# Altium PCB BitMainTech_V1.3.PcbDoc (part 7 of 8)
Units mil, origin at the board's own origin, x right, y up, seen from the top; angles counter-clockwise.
Board outline 9842.52 x 6082.68 mil, 4 copper layers (Top Layer, Mid-Layer 1, Mid-Layer 2, Bottom Layer); 987 components, 282 nets, 3694 pads, 3174 vias.
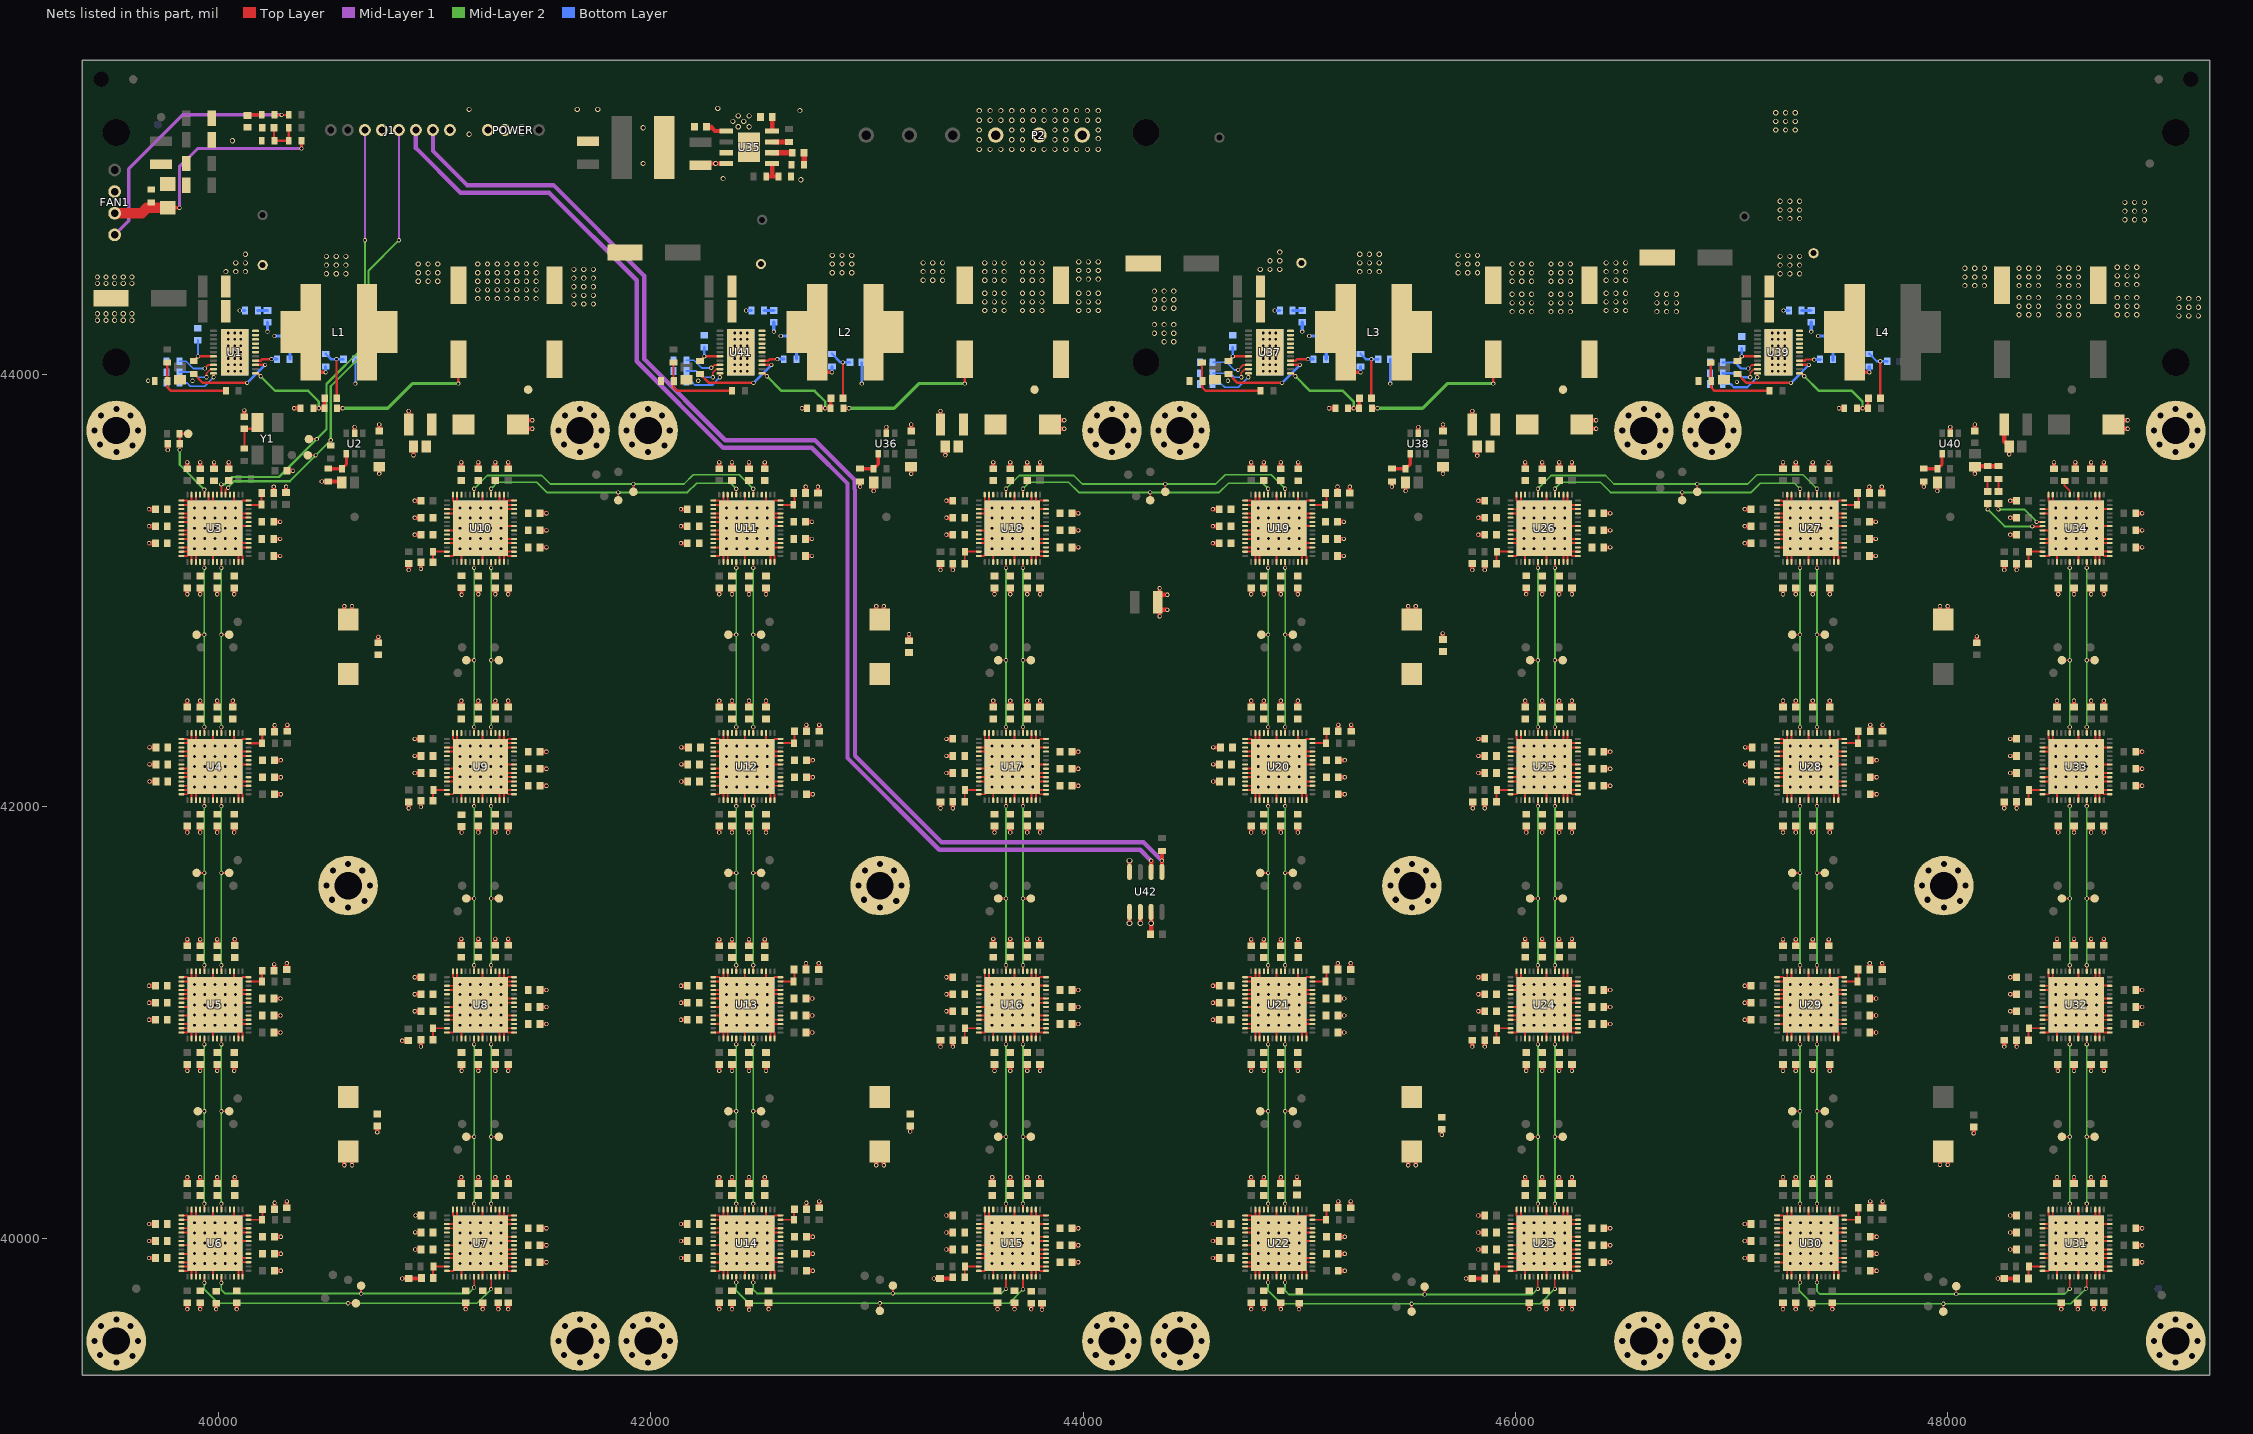
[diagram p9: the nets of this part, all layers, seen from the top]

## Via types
v1: diameter 19, hole 12, Top Layer to Bottom Layer, 1347 vias
v2: diameter 25.98, hole 12.99, Top Layer to Bottom Layer, 800 vias
v3: diameter 24, hole 16, Top Layer to Bottom Layer, 778 vias
v4: diameter 50, hole 28, Top Layer to Bottom Layer, 160 vias
v5: diameter 19.68, hole 11.81, Top Layer to Bottom Layer, 84 vias
v6: diameter 26, hole 18, Top Layer to Bottom Layer, 5 vias

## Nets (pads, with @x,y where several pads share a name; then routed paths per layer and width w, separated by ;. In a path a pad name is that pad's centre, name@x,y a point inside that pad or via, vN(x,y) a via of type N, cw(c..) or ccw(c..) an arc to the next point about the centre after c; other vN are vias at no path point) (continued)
GND: (continued)
  other v4: 39527.56,39427.56 41673.23,39427.56 41988.19,39427.56 44133.86,39427.56 44448.82,39427.56 46594.49,39427.56 46909.45,39427.56 49055.12,39427.56 39602.56,39457.56 41748.23,39457.56 42063.19,39457.56 44208.86,39457.56 44523.82,39457.56 46669.49,39457.56 46984.45,39457.56 49130.12,39457.56 39452.56,39462.56 41598.23,39462.56 41913.19,39462.56 44058.86,39462.56 44373.82,39462.56 46519.49,39462.56 46834.45,39462.56 48980.12,39462.56 39427.56,39527.56 39627.56,39527.56 41573.23,39527.56 41773.23,39527.56 41888.19,39527.56 42088.19,39527.56 44033.86,39527.56 44233.86,39527.56 44348.82,39527.56 44548.82,39527.56 46494.49,39527.56 46694.49,39527.56 46809.45,39527.56 47009.45,39527.56 48955.12,39527.56 49155.12,39527.56 39457.56,39597.56 39592.56,39597.56 41603.23,39597.56 41738.23,39597.56 41918.19,39597.56 42053.19,39597.56 44063.86,39597.56 44198.86,39597.56 44378.82,39597.56 44513.82,39597.56 46524.49,39597.56 46659.49,39597.56 46839.45,39597.56 46974.45,39597.56 48985.12,39597.56 49120.12,39597.56 39527.56,39627.56 41673.23,39627.56 41988.19,39627.56 44133.86,39627.56 44448.82,39627.56 46594.49,39627.56 46909.45,39627.56 49055.12,39627.56 40600.39,41533.86 43061.02,41533.86 45521.67,41533.86 47982.28,41533.86 40675.39,41563.86 43136.02,41563.86 45596.67,41563.86 48057.28,41563.86 40525.39,41568.86 42986.02,41568.86 45446.67,41568.86 47907.28,41568.86 40500.39,41633.86 40700.39,41633.86 42961.02,41633.86 43161.02,41633.86 45421.67,41633.86 45621.67,41633.86 47882.28,41633.86 48082.28,41633.86 40530.39,41703.86 40665.39,41703.86 42991.02,41703.86 43126.02,41703.86 45451.67,41703.86 45586.67,41703.86 47912.28,41703.86 48047.28,41703.86 40600.39,41733.86 43061.02,41733.86 45521.67,41733.86 47982.28,41733.86 39527.56,43640.16 41673.23,43640.16 41988.19,43640.16 44133.86,43640.16 44448.82,43640.16 46594.49,43640.16 46909.45,43640.16 49055.12,43640.16 39602.56,43670.16 41748.23,43670.16 42063.19,43670.16 44208.86,43670.16 44523.82,43670.16 46669.49,43670.16 46984.45,43670.16 49130.12,43670.16 39452.56,43675.16 41598.23,43675.16 41913.19,43675.16 44058.86,43675.16 44373.82,43675.16 46519.49,43675.16 46834.45,43675.16 48980.12,43675.16 39427.56,43740.16 39627.56,43740.16 41573.23,43740.16 41773.23,43740.16 41888.19,43740.16 42088.19,43740.16 44033.86,43740.16 44233.86,43740.16 44348.82,43740.16 44548.82,43740.16 46494.49,43740.16 46694.49,43740.16 46809.45,43740.16 47009.45,43740.16 48955.12,43740.16 49155.12,43740.16 39457.56,43810.16 39592.56,43810.16 41603.23,43810.16 41738.23,43810.16 41918.19,43810.16 42053.19,43810.16 44063.86,43810.16 44198.86,43810.16 44378.82,43810.16 44513.82,43810.16 46524.49,43810.16 46659.49,43810.16 46839.45,43810.16 46974.45,43810.16 48985.12,43810.16 49120.12,43810.16 39527.56,43840.16 41673.23,43840.16 41988.19,43840.16 44133.86,43840.16 44448.82,43840.16 46594.49,43840.16 46909.45,43840.16 49055.12,43840.16
  other v5: 40045.28,44013.78 40074.8,44013.78 40104.33,44013.78 42387.8,44013.78 42417.32,44013.78 42446.85,44013.78 44833.46,44013.78 44862.99,44013.78 44892.52,44013.78 47187.8,44013.78 47217.32,44013.78 47246.85,44013.78 40045.28,44043.31 40074.8,44043.31 40104.33,44043.31 42387.8,44043.31 42417.32,44043.31 42446.85,44043.31 44833.46,44043.31 44862.99,44043.31 44892.52,44043.31 47187.8,44043.31 47217.32,44043.31 47246.85,44043.31 40045.28,44072.83 40074.8,44072.83 40104.33,44072.83 42387.8,44072.83 42417.32,44072.83 42446.85,44072.83 44833.46,44072.83 44862.99,44072.83 44892.52,44072.83 47187.8,44072.83 47217.32,44072.83 47246.85,44072.83 40045.28,44102.36 40074.8,44102.36 40104.33,44102.36 42387.8,44102.36 42417.32,44102.36 42446.85,44102.36 44833.46,44102.36 44862.99,44102.36 44892.52,44102.36 47187.8,44102.36 47217.32,44102.36 47246.85,44102.36 40045.28,44131.89 40074.8,44131.89 40104.33,44131.89 42387.8,44131.89 42417.32,44131.89 42446.85,44131.89 44833.46,44131.89 44862.99,44131.89 44892.52,44131.89 47187.8,44131.89 47217.32,44131.89 47246.85,44131.89 40045.28,44161.42 40074.8,44161.42 40104.33,44161.42 42387.8,44161.42 42417.32,44161.42 42446.85,44161.42 44833.46,44161.42 44862.99,44161.42 44892.52,44161.42 47187.8,44161.42 47217.32,44161.42 47246.85,44161.42 40045.28,44190.94 40074.8,44190.94 40104.33,44190.94 42387.8,44190.94 42417.32,44190.94 42446.85,44190.94 44833.46,44190.94 44862.99,44190.94 44892.52,44190.94 47187.8,44190.94 47217.32,44190.94 47246.85,44190.94
  other v6: 44315,41460
LL1: C11.2 C12.1 L1.1 R1.1 U1.6 U1.7 U1.8 U1.9 U1.10 U1.11 | length 183
  Top Layer w15: L1.1@40454,44009 v1(40496.06,44009)
  Bottom Layer w15: v1(40227,44197) C12.1@40227,44240.44 ; v1@40259,44177.17 C11.2@40330,44177.17 ; v1(40496.06,44009) R1.1@40496.06,44035.47
  other v1: 40259,44177
LL2: C558.2 C559.1 L2.1 R64.1 U41.6 U41.7 U41.8 U41.9 U41.10 U41.11 | length 185.5
  Top Layer w15: L2.1@42796.52,44009 v1(42838.58,44009)
  Bottom Layer w15: v1(42569.52,44197) C559.1@42569.52,44240.44 ; v1@42601.52,44177.17 C558.2@42675,44177.17 ; v1(42838.58,44009) R64.1@42838.58,44035.47
  other v1: 42601.52,44177
LL3: C574.2 C575.1 L3.1 R36.1 U37.6 U37.7 U37.8 U37.9 U37.10 U37.11 | length 190.6
  Top Layer w15: L3.1@45241.4,44009 v1(45283.46,44009)
  Bottom Layer w15: v1(45014.4,44197) C575.1@45014.4,44240.44 ; v1@45046.4,44177.17 C574.2@45125,44177.17 ; v1(45283.46,44009) R36.1@45283.46,44035.47
  other v1: 45046.4,44177
LL4: C590.2 C591.1 L4.1 R50.1 U39.6 U39.7 U39.8 U39.9 U39.10 U39.11 | length 181.2
  Top Layer w15: L4.1@47595.73,44009 v1(47637.8,44009)
  Bottom Layer w15: v1(47368.73,44197) C591.1@47368.73,44240.44 ; v1@47400.73,44177.17 C590.2@47470,44177.17 ; v1(47637.8,44009) R50.1@47637.8,44035.47
  other v1: 47400.73,44177
NetC1_2: C1.2 C10.1 R1.2 | length 273.1
  Top Layer w11: v1(40546.54,44070) C10.1@40547.24,43889.76
  Bottom Layer w11: R1.2@40496.06,44094.53 40520.59,44070 v1(40546.54,44070) C1.2@40578.74,44070
NetC10_2: C10.2 R3.2 R12.1 U1.1 | length 474.3
  Top Layer w11: U1.1@40172.05,44003.94 40182.06,44003.94 v1(40195,43991)
  Top Layer w15: R12.1@40438.98,43842.52 R3.2@40490.16,43842.52 C10.2@40490.16,43887.8
  Mid-Layer 2 w11: v1(40195,43991) 40263,43923 40415.58,43923 40464.57,43874.02 v1(40464.57,43842.52)
NetC11_1: C11.1 R4.2 | length 52.4
  Bottom Layer w15: R4.2@40330.71,44070 C11.1@40330.71,44122.44
NetC12_2: C12.2 R11.1 | length 43.9
  Bottom Layer w15: R11.1@40182.53,44295 C12.2@40226.44,44295
NetC13_1: C13.1 R6.1 U1.18 | length 174.7
  Top Layer w11: R6.1@39885.83,44062.99 v1(39905.51,44082.68) U1.18@39977.56,44082.68
  Bottom Layer w11: v1(39905.51,44082.68) C13.1@39905.51,44157.44
NetC22_2: C22.2 FB1.1 U3.55 | length 108.3
  Top Layer w10: U3.55@40139.76,43395.67 FB1.1@40196.85,43395.67 ; FB1.1@40198.82,43397.64 C22.2@40198.82,43448.82
NetC24_2: C24.2 FB2.1 U4.55 | length 114.2
  Top Layer w10: U4.55@40139.76,42293.31 FB2.1@40202.76,42293.31 C24.2@40202.76,42344.49
NetC26_2: C26.2 FB3.1 U5.55 | length 108.3
  Top Layer w10: U5.55@40139.76,41190.94 FB3.1@40200.79,41190.94 C26.2@40200.79,41238.19
NetC28_2: C28.2 FB4.1 U6.55 | length 114.2
  Top Layer w9: U6.55@40139.76,40088.58 40204.72,40088.58 C28.2@40204.72,40137.8
NetC30_1: C30.1 R17.2 Y1.3 | length 131.9
  Top Layer w10: R17.2@40120.08,43657.48 C30.1@40120.08,43748.03 Y1.3@40161.42,43748.03
NetC89_2: C89.2 FB5.1 U7.55 | length 114.2
  Top Layer w9: C89.2@40992.13,39822.83 40992.13,39872.05 U7.55@41057.09,39872.05
NetC91_2: C91.2 FB6.1 U8.55 | length 114.2
  Top Layer w9: C91.2@40992.13,40925.2 FB6.1@40992.13,40974.41 U8.55@41057.09,40974.41
NetC93_2: C93.2 FB7.1 U9.55 | length 114.2
  Top Layer w9: C93.2@40992.13,42027.56 40992.13,42076.77 U9.55@41057.09,42076.77
NetC95_2: C95.2 FB8.1 U10.55 | length 114.2
  Top Layer w9: C95.2@40992.13,43129.92 FB8.1@40992.13,43179.13 U10.55@41057.09,43179.13
NetC157_2: C157.2 FB9.1 U11.55 | length 114.2
  Top Layer w9: U11.55@42600.39,43395.67 42665.35,43395.67 C157.2@42665.35,43444.88
NetC159_2: C159.2 FB10.1 U12.55 | length 114.2
  Top Layer w9: U12.55@42600.39,42293.31 42665.35,42293.31 C159.2@42665.35,42342.52
NetC161_2: C161.2 FB11.1 U13.55 | length 114.2
  Top Layer w9: U13.55@42600.39,41190.94 42665.35,41190.94 C161.2@42665.35,41240.16
NetC163_2: C163.2 FB12.1 U14.55 | length 110.2
  Top Layer w9: U14.55@42600.39,40088.58 FB12.1@42663.39,40088.58 C163.2@42663.39,40135.83
NetC221_2: C221.2 FB13.1 U15.55 | length 114.2
  Top Layer w9: C221.2@43452.76,39822.83 43452.76,39872.05 U15.55@43517.72,39872.05
NetC223_2: C223.2 FB14.1 U16.55 | length 114.2
  Top Layer w9: C223.2@43452.76,40925.2 43452.76,40974.41 U16.55@43517.72,40974.41
NetC225_2: C225.2 FB15.1 U17.55 | length 114.2
  Top Layer w9: C225.2@43452.76,42027.56 43452.76,42076.77 U17.55@43517.72,42076.77
NetC227_2: C227.2 FB16.1 U18.55 | length 114.2
  Top Layer w9: C227.2@43452.76,43129.92 43452.76,43179.13 U18.55@43517.72,43179.13
NetC289_2: C289.2 FB17.1 U19.55 | length 114.2
  Top Layer w9: U19.55@45061.02,43395.67 45125.98,43395.67 C289.2@45125.98,43444.88
NetC291_2: C291.2 FB18.1 U20.55 | length 114.2
  Top Layer w9: U20.55@45061.02,42293.31 45125.98,42293.31 C291.2@45125.98,42342.52
NetC293_2: C293.2 FB19.1 U21.55 | length 114.2
  Top Layer w9: U21.55@45061.02,41190.94 45125.98,41190.94 C293.2@45125.98,41240.16
NetC295_2: C295.2 FB20.1 U22.55 | length 114.2
  Top Layer w9: U22.55@45061.02,40088.58 45125.98,40088.58 C295.2@45125.98,40137.8
NetC353_2: C353.2 FB21.1 U23.55 | length 114.2
  Top Layer w9: C353.2@45913.39,39822.83 45913.39,39872.05 U23.55@45978.35,39872.05
NetC355_2: C355.2 FB22.1 U24.55 | length 114.2
  Top Layer w9: C355.2@45913.39,40925.2 45913.39,40974.41 U24.55@45978.35,40974.41
NetC357_2: C357.2 FB23.1 U25.55 | length 114.2
  Top Layer w9: C357.2@45913.39,42027.56 45913.39,42076.77 U25.55@45978.35,42076.77
NetC359_2: C359.2 FB24.1 U26.55 | length 114.2
  Top Layer w9: C359.2@45913.39,43129.92 45913.39,43179.13 U26.55@45978.35,43179.13
NetC421_2: C421.2 FB25.1 U27.55 | length 114.2
  Top Layer w9: U27.55@47521.65,43395.67 47586.61,43395.67 C421.2@47586.61,43444.88
NetC423_2: C423.2 FB26.1 U28.55 | length 114.2
  Top Layer w9: U28.55@47521.65,42293.31 47586.61,42293.31 C423.2@47586.61,42342.52
NetC425_2: C425.2 FB27.1 U29.55 | length 114.2
  Top Layer w9: U29.55@47521.65,41190.94 47586.61,41190.94 C425.2@47586.61,41240.16
NetC427_2: C427.2 FB28.1 U30.55 | length 114.2
  Top Layer w9: U30.55@47521.65,40088.58 47586.61,40088.58 C427.2@47586.61,40137.8
NetC485_2: C485.2 FB29.1 U31.55 | length 114.2
  Top Layer w9: C485.2@48374.02,39822.83 48374.02,39872.05 U31.55@48438.98,39872.05
NetC487_2: C487.2 FB30.1 U32.55 | length 114.2
  Top Layer w9: C487.2@48374.02,40925.2 48374.02,40974.41 U32.55@48438.98,40974.41
NetC489_2: C489.2 FB31.1 U33.55 | length 114.2
  Top Layer w9: C489.2@48374.02,42027.56 48374.02,42076.77 U33.55@48438.98,42076.77
NetC491_2: C491.2 FB32.1 U34.55 | length 114.2
  Top Layer w9: C491.2@48374.02,43129.92 48374.02,43179.13 U34.55@48438.98,43179.13
NetC549_2: C549.2 D1.2 FAN1.2 FB33.1 FB34.1 R70.2
NetC551_1: C551.1 U35.1 | length 99.4
  Top Layer w20: C551.1@42257.56,45145 42277.56,45145 42297.56,45125 U35.1@42348.7,45125
NetC551_2: C551.2 L5.1 U35.3
NetC552_1: C552.1 U35.8 | length 63.7
  Top Layer w20: U35.8@42562.56,45126.26 C552.1@42562.56,45190
NetC557_1: C557.1 C598.2 R64.2 | length 264.3
  Top Layer w11: C557.1@42889.76,43889.76 v1@42889.76,44055
  Bottom Layer w11: R64.2@42838.58,44094.53 42878.11,44055 v1(42889.06,44055) C598.2@42921.26,44055
NetC557_2: C557.2 R33.1 R66.2 U41.1 | length 474.3
  Top Layer w11: U41.1@42514.57,44003.94 42524.58,44003.94 v1(42537.52,43991)
  Top Layer w15: R33.1@42781.5,43842.52 R66.2@42832.68,43842.52 C557.2@42832.68,43887.8
  Mid-Layer 2 w11: v1(42537.52,43991) 42605.52,43923 42758.1,43923 42807.09,43874.02 v1(42807.09,43842.52)
NetC558_1: C558.1 R67.2 | length 59.1
  Bottom Layer w15: R67.2@42674.53,44070 C558.1@42674.53,44129.06
NetC559_2: C559.2 R32.1 | length 43.9
  Bottom Layer w15: R32.1@42525.05,44295 C559.2@42568.96,44295
NetC560_1: C560.1 R69.1 U41.18 | length 142.2
  Top Layer w11: R69.1@42228.35,44062.99 v1(42248.03,44082.68) U41.18@42320.08,44082.68
  Bottom Layer w11: v1(42248.03,44082.68) C560.1@42248.03,44125
NetC564_2: C564.2 C573.1 R36.2 | length 272.8
  Top Layer w11: C573.1@45333.94,43890 v1(45333.94,44070)
  Bottom Layer w11: R36.2@45283.46,44094.53 45307.99,44070 v1(45333.94,44070) C564.2@45366.14,44070
NetC573_2: C573.2 R38.2 R47.1 U37.1 | length 474.3
  Top Layer w11: U37.1@44959.45,44003.94 44969.46,44003.94 v1(44982.4,43991)
  Top Layer w15: R47.1@45226.38,43842.52 R38.2@45277.56,43842.52 C573.2@45277.56,43887.8
  Mid-Layer 2 w11: v1(44982.4,43991) 45050.4,43923 45202.98,43923 45251.97,43874.02 v1(45251.97,43842.52)
NetC574_1: C574.1 R39.2 | length 52.4
  Bottom Layer w15: R39.2@45125,44070 C574.1@45125,44122.44
NetC575_2: C575.2 R46.1 | length 43.9
  Bottom Layer w15: R46.1@44969.93,44295 C575.2@45013.84,44295
NetC576_1: C576.1 R41.1 U37.18 | length 142.2
  Top Layer w11: R41.1@44673.23,44062.99 v1(44692.91,44082.68) U37.18@44764.96,44082.68
  Bottom Layer w11: v1(44692.91,44082.68) C576.1@44692.91,44125
NetC580_2: C580.2 C589.1 R50.2 | length 267
  Top Layer w11: C589.1@47688.28,43890 v1(47688.28,44060)
  Bottom Layer w11: R50.2@47637.8,44094.53 47672.32,44060 v1(47688.28,44060) C580.2@47720.47,44060
NetC589_2: C589.2 R52.2 R61.1 U39.1 | length 474.3
  Top Layer w11: U39.1@47313.78,44003.94 47323.8,44003.94 v1(47336.73,43991)
  Top Layer w15: R61.1@47580.71,43842.52 R52.2@47631.89,43842.52 C589.2@47631.89,43887.8
  Mid-Layer 2 w11: v1(47336.73,43991) 47404.73,43923 47557.31,43923 47606.3,43874.02 v1(47606.3,43842.52)
NetC590_1: C590.1 R53.2 | length 57.4
  Bottom Layer w15: R53.2@47470,44065 C590.1@47470,44122.44
NetC591_2: C591.2 R60.1 | length 43.9
  Bottom Layer w15: R60.1@47324.26,44295 C591.2@47368.17,44295
NetC592_1: C592.1 R55.1 U39.18 | length 137.2
  Top Layer w11: R55.1@47027.56,44062.99 v1(47047.24,44082.68) U39.18@47119.29,44082.68
  Bottom Layer w11: v1(47047.24,44082.68) C592.1@47047.24,44120
NetC603_1: C603.1 U35.6 | length 91.9
  Top Layer w24: U35.6@42562.52,45025 C603.1@42654.41,45025
NetC603_2: C603.2 R73.2 | length 55
  Top Layer w25: R73.2@42709.53,44970 C603.2@42709.53,45025
NetC604_1: C604.1 R23.2 R24.1 R25.2 | length 184
  Top Layer w10: R25.2@40257.56,45081.97 C604.1@40257.56,45140 ; R25.2@40259.53,45080 R23.2@40325.47,45080 R24.1@40325.47,45140
NetC605_1: C605.1 R26.1 | length 63
  Top Layer w15: C605.1@40137.44,45200 R26.1@40200.47,45200
NetD1_1: D1.1 FAN1.3 R23.1 R70.1 | length 1135.4
  Top Layer w15: D1.1@39765,44769.88 v1(39819.88,44769.88) ; v1(40384.53,45044.53) R23.1@40384.53,45080
  Top Layer w50: FAN1.3@39520,44745 39645,44745 39669.88,44769.88 D1.1@39765,44769.88
  Mid-Layer 1 w15: v1(39819.88,44769.88) 39819.88,44959.88 39904.53,45044.53 v1(40384.53,45044.53)
NetFAN1_4: FAN1.4 R26.2 R27.1 | length 1208.9
  Top Layer w10: R26.2@40259.53,45200 R27.1@40325.47,45200
  Mid-Layer 1 w15: FAN1.4@39520,44645 39585,44710 39585,44950 39835,45200 v1(40292.5,45200)
NetR2_2: R2.2 R5.1 R7.1 | length 390.8
  Top Layer w11: R7.1@39763,43970.53 R2.2@39763,44054.47 ; R7.1@39764.53,43969 39764.53,43938.47 39780,43923 R5.1@40034.47,43923
NetR4_1: R4.1 U1.4 | length 101.3
  Top Layer w11: U1.4@40172.05,44062.99 40196.99,44062.99 40204,44070 v1(40245.5,44070)
  Bottom Layer w15: v1(40245.5,44070) R4.1@40270.47,44070
NetR6_2: R6.2 U1.3 | length 426.1
  Top Layer w11: R6.2@39885.83,44001.97 39927.8,43960 v1(40133,43960) ; U1.3@40172.05,44043.31 v1(40216,44043.31)
  Bottom Layer w11: v1@40132.85,43960.15 v1(40216,44043.31)
NetR8_1: R8.1 U1.20 | length 178.7
  Top Layer w8: v1(39936.65,44026.65) 39953.31,44043.31 U1.20@39977.56,44043.31
  Bottom Layer w8: R8.1@39819.53,44060 39850,44060 39883.35,44026.65 v1(39936.65,44026.65)
NetR9_1: R9.1 U1.22 | length 199.2
  Top Layer w8: v1(39977.56,43986) U1.22@39977.56,44003.94
  Bottom Layer w8: R9.1@39819.53,43960 39855,43960 39870,43945 39936.56,43945 v1(39977.56,43986)
NetR10_1: R10.1 U1.21 | length 194.7
  Top Layer w8: v1@39944.88,43986 39944.88,44004.88 39963.62,44023.62 U1.21@39977.56,44023.62
  Bottom Layer w8: R10.1@39819.53,44010 39880,44010 39904,43986 v1(39945,43986)
NetR13_1: R13.1 R14.2 U2.4 | length 140.9
  Top Layer w15: R14.2@40507.87,43562.99 R13.1@40570.87,43562.99 40592.52,43584.65 U2.4@40592.52,43631.89
NetR19_2: R19.2 TF.2 | length 57.9
  Top Layer w10: TF.2@48235,43457.56 R19.2@48235,43515.47
NetR20_2: R20.2 RF.2 | length 57.9
  Top Layer w10: RF.2@48185,43457.56 R20.2@48185,43515.47
NetR22_1: R22.1 U35.7 | length 77.5
  Top Layer w23: U35.7@42562.52,45075 R22.1@42640,45075
NetR28_1: R28.1 R65.2 R68.1 | length 390.8
  Top Layer w11: R28.1@42105.52,43970.53 R65.2@42105.52,44054.47 ; R28.1@42107.05,43969 42107.05,43938.47 42122.52,43923 R68.1@42376.99,43923
NetR29_1: R29.1 U41.20 | length 179.8
  Top Layer w8: v1(42279.98,44030) 42279.98,44027.47 42295.83,44043.31 U41.20@42320.08,44043.31
  Bottom Layer w8: R29.1@42164.53,44065 42200,44065 42235.81,44029.19 42279.17,44029.19 v1(42279.98,44030)
NetR30_1: R30.1 U41.22 | length 194.6
  Top Layer w8: v1(42320.08,43986) U41.22@42320.08,44003.94
  Bottom Layer w8: R30.1@42164.53,43965 42190,43965 42205,43950 42284.08,43950 v1(42320.08,43986)
NetR31_1: R31.1 U41.21 | length 195.8
  Top Layer w8: v1@42287.4,43986 42287.4,44007.4 42303.62,44023.62 U41.21@42320.08,44023.62
  Bottom Layer w8: R31.1@42164.53,44015 42210,44015 42239,43986 v1(42287.52,43986)
NetR34_1: R34.1 R35.2 U36.4 | length 140.9
  Top Layer w15: R35.2@42968.5,43562.99 R34.1@43031.5,43562.99 43053.15,43584.65 U36.4@43053.15,43631.89
NetR37_2: R37.2 R40.1 R42.1 | length 390.8
  Top Layer w11: R42.1@44550.4,43970.53 R37.2@44550.4,44054.47 ; R42.1@44551.93,43969 44551.93,43938.47 44567.4,43923 R40.1@44821.87,43923
NetR39_1: R39.1 U37.4 | length 108.9
  Top Layer w11: U37.4@44959.45,44062.99 44984.39,44062.99 44991.4,44070 v1(45041,44070)
  Bottom Layer w15: v1(45041,44070) R39.1@45065.47,44070
NetR41_2: R41.2 U37.3 | length 426.1
  Top Layer w11: R41.2@44673.23,44001.97 44715.2,43960 v1(44920.4,43960) ; U37.3@44959.45,44043.31 v1(45003.4,44043.31)
  Bottom Layer w11: v1@44920.25,43960.15 v1(45003.4,44043.31)
NetR43_1: R43.1 U37.20 | length 189.6
  Top Layer w8: v1(44717.4,44020) 44740.71,44043.31 U37.20@44764.96,44043.31
  Bottom Layer w8: R43.1@44599.53,44055 44665,44055 44700,44020 v1(44717.4,44020)
NetR44_1: R44.1 U37.22 | length 208.6
  Top Layer w8: v1(44764.96,43986) U37.22@44764.96,44003.94
  Bottom Layer w8: R44.1@44599.53,43955 44640,43955 44655,43940 44718.96,43940 v1(44764.96,43986)
NetR45_1: R45.1 U37.21 | length 201.5
  Top Layer w8: v1@44732.28,43986 44732.28,44007.28 44748.62,44023.62 U37.21@44764.96,44023.62
  Bottom Layer w8: R45.1@44599.53,44005 44680,44005 44699,43986 v1(44732.4,43986)
NetR48_1: R48.1 R49.2 U38.4 | length 140.9
  Top Layer w15: R49.2@45429.13,43562.99 R48.1@45492.13,43562.99 45513.78,43584.65 U38.4@45513.78,43631.89
NetR51_2: R51.2 R54.1 R56.1 | length 390.8
  Top Layer w11: R56.1@46904.73,43970.53 R51.2@46904.73,44054.47 ; R56.1@46906.26,43969 46906.26,43938.47 46921.73,43923 R54.1@47176.2,43923
NetR53_1: R53.1 U39.4 | length 103
  Top Layer w11: U39.4@47313.78,44062.99 47338.72,44062.99 47343.73,44068 v1(47382,44068) v1@47385,44065
  Bottom Layer w15: v1(47382,44068) R53.1@47410.47,44068
NetR55_2: R55.2 U39.3 | length 426.1
  Top Layer w11: R55.2@47027.56,44001.97 47069.53,43960 v1(47274.73,43960) ; U39.3@47313.78,44043.31 v1(47357.73,44043.31)
  Bottom Layer w11: v1@47274.58,43960.15 v1(47357.73,44043.31)
NetR57_1: R57.1 U39.20 | length 178.4
  Top Layer w8: v1(47078.39,44026.65) 47095.04,44043.31 U39.20@47119.29,44043.31
  Bottom Layer w10: R57.1@46959.53,44055 47015.86,44055 47044.21,44026.65 v1(47078.39,44026.65)
NetR58_1: R58.1 U39.22 | length 203
  Top Layer w8: v1(47119.29,43986) U39.22@47119.29,44003.94
  Bottom Layer w10: R58.1@46959.53,43955 46995,43955 47010,43940 47073.29,43940 v1(47119.29,43986)
NetR59_1: R59.1 U39.21 | length 195.4
  Top Layer w8: v1@47086.61,43986 47086.61,44006.61 47103.62,44023.62 U39.21@47119.29,44023.62
  Bottom Layer w10: R59.1@46959.53,44005 47030,44005 47049,43986 v1(47086.73,43986)
NetR62_1: R62.1 R63.2 U40.4 | length 140.9
  Top Layer w15: R63.2@47889.76,43562.99 R62.1@47952.76,43562.99 47974.41,43584.65 U40.4@47974.41,43631.89
NetR67_1: R67.1 U41.4 | length 103.8
  Top Layer w11: U41.4@42514.57,44062.99 42545,44062.99 42552.01,44070 v1(42585.99,44070)
  Bottom Layer w15: v1(42585.99,44070) R67.1@42615.47,44070
NetR69_2: R69.2 U41.3 | length 426.1
  Top Layer w11: R69.2@42228.35,44001.97 42270.32,43960 v1(42475.52,43960) ; U41.3@42514.57,44043.31 v1(42558.52,44043.31)
  Bottom Layer w11: v1@42475.37,43960.15 v1(42558.52,44043.31)
NetR71_2: R71.2 R72.2 U35.5 | length 110
  Top Layer w20: R71.2@42535,44914.53 R72.2@42590,44914.53 ; 42562.52,44920 U35.5@42562.52,44975
NetRF_1: RF.1 U34.49 | length 314.3
  Top Layer w10: v1(48185,43375) RF.1@48185,43402.44 ; v1(48391.43,43296.43) 48438.16,43296.43 U34.49@48438.98,43297.24
  Mid-Layer 2 w10: v1(48185,43375) 48263.57,43296.43 v1(48391.43,43296.43)
NetTF_1: TF.1 U34.48 | length 255.5
  Top Layer w10: v1(48235,43375) TF.1@48235,43402.44 ; v1(48411.93,43316.93) U34.48@48438.98,43316.93
  Mid-Layer 2 w10: v1(48235,43375) 48353.86,43375 v1(48411.93,43316.93)
RI1: TP10.1 U3.37 U4.6 | length 827.5
  Top Layer w8: U4.6@40013.78,42340.55 v1(40013.78,42368.11) ; v1(40013.78,42795.28) TP10.1@40049.96,42795.28 ; v1(40013.78,43104.33) U3.37@40013.78,43131.89
  Mid-Layer 2 w8: v1(40013.78,42368.11) v1(40013.78,43104.33)
RI2: TP12.1 U4.37 U5.6 | length 827.5
  Top Layer w8: U5.6@40013.78,41238.19 v1(40013.78,41265.75) ; v1(40013.78,41692.91) TP12.1@40049.96,41692.91 ; v1(40013.78,42001.97) U4.37@40013.78,42029.53
  Mid-Layer 2 w8: v1(40013.78,41265.75) v1(40013.78,42001.97)
RI3: TP14.1 U5.37 U6.6 | length 827.5
  Top Layer w8: U6.6@40013.78,40135.83 v1(40013.78,40163.39) ; v1(40013.78,40590.55) TP14.1@40049.96,40590.55 ; v1(40013.78,40899.61) U5.37@40013.78,40927.17
  Mid-Layer 2 w8: v1(40013.78,40163.39) v1(40013.78,40899.61)
RI4: TP16.1 U6.37 U7.6 | length 1334.6
  Top Layer w8: v1(40013.78,39797.24) U6.37@40013.78,39824.8 ; v1(40660,39747) TP16.1@40660,39783.18 ; v1(41183.07,39775) U7.6@41183.07,39824.8
  Mid-Layer 2 w8: v1(40013.78,39797.24) 40013.78,39764.22 40031,39747 41155.07,39747 v1(41183.07,39775)
RI5: TP34.1 U7.37 U8.6 | length 882.6
  Top Layer w8: TP34.1@41146.89,40472.44 v1(41183.07,40472.44) ; U7.37@41183.07,40135.83 v1(41183.07,40163.39) U7.37@41183.07,40135.83 ; v1(41183.07,40899.61) U8.6@41183.07,40927.17 v1(41183.07,40899.61)
  Mid-Layer 2 w8: v1(41183.07,40163.39) v1(41183.07,40899.61)
RI6: TP36.1 U8.37 U9.6 | length 882.6
  Top Layer w8: TP36.1@41146.89,41574.8 v1(41183.07,41574.8) ; U8.37@41183.07,41238.19 v1(41183.07,41265.75) U8.37@41183.07,41238.19 ; v1(41183.07,42001.97) U9.6@41183.07,42029.53 v1(41183.07,42001.97)
  Mid-Layer 2 w8: v1(41183.07,41265.75) v1(41183.07,42001.97)
RI7: TP38.1 U9.37 U10.6 | length 827.5
  Top Layer w8: TP38.1@41146.89,42677.17 v1(41183.07,42677.17) ; U9.37@41183.07,42340.55 v1(41183.07,42368.11) ; v1(41183.07,43104.33) U10.6@41183.07,43131.89
  Mid-Layer 2 w8: v1(41183.07,42368.11) v1(41183.07,43104.33)
RI8: TP40.1 U10.37 U11.6 | length 1468.9
  Top Layer w8: U10.37@41183.07,43442.91 v1(41183.07,43470.47) ; TP40.1@41920,43456.13 v1(41920,43492.31) ; U11.6@42474.41,43442.91 v1(42474.41,43470.47)
  Mid-Layer 2 w8: v1(41183.07,43470.47) 41244.09,43531.5 41496.06,43531.5 41535.25,43492.31 42153.73,43492.31 42196.85,43535.43 42409.45,43535.43 v1(42474.41,43470.47)
RI9: TP54.1 U11.37 U12.6 | length 882.6
  Top Layer w8: v1(42474.41,42795.28) TP54.1@42510.59,42795.28 ; U12.6@42474.41,42340.55 v1(42474.41,42368.11) U12.6@42474.41,42340.55 ; v1(42474.41,43104.33) U11.37@42474.41,43131.89 v1(42474.41,43104.33)
  Mid-Layer 2 w8: v1(42474.41,42368.11) v1(42474.41,43104.33)
RI10: TP56.1 U12.37 U13.6 | length 882.6
  Top Layer w8: v1(42474.41,41692.91) TP56.1@42510.59,41692.91 ; U13.6@42474.41,41238.19 v1(42474.41,41265.75) U13.6@42474.41,41238.19 ; v1(42474.41,42001.97) U12.37@42474.41,42029.53 v1(42474.41,42001.97)
  Mid-Layer 2 w8: v1(42474.41,41265.75) v1(42474.41,42001.97)
RI11: TP58.1 U13.37 U14.6 | length 882.6
  Top Layer w8: v1(42474.41,40590.55) TP58.1@42510.59,40590.55 ; U14.6@42474.41,40135.83 v1(42474.41,40163.39) U14.6@42474.41,40135.83 ; v1(42474.41,40899.61) U13.37@42474.41,40927.17 v1(42474.41,40899.61)
  Mid-Layer 2 w8: v1(42474.41,40163.39) v1(42474.41,40899.61)
RI12: TP60.1 U14.37 U15.6 | length 1338.9
  Top Layer w8: v1(42474.22,39798.05) U14.37@42474.22,39825.61 ; v1(43120.44,39747.8) TP60.1@43120.44,39783.98 ; v1(43643.51,39768.46) U15.6@43643.51,39825.61
  Mid-Layer 2 w8: v1(42474.22,39798.05) 42474.22,39765.02 42491.44,39747.8 43622.85,39747.8 v1(43643.51,39768.46)
RI13: TP76.1 U15.37 U16.6 | length 855.1
  Top Layer w8: TP76.1@43607.52,40472.44 v1(43643.7,40472.44) ; U15.37@43643.7,40135.83 v1(43643.7,40163.39) ; v1(43643.7,40899.61) U16.6@43643.7,40927.17 v1(43643.7,40899.61)
  Mid-Layer 2 w8: v1(43643.7,40163.39) v1(43643.7,40899.61)
RI14: TP78.1 U16.37 U17.6 | length 882.6
  Top Layer w8: TP78.1@43607.52,41574.8 v1(43643.7,41574.8) ; U16.37@43643.7,41238.19 v1(43643.7,41265.75) U16.37@43643.7,41238.19 ; v1(43643.7,42001.97) U17.6@43643.7,42029.53 v1(43643.7,42001.97)
  Mid-Layer 2 w8: v1(43643.7,41265.75) v1(43643.7,42001.97)
RI15: TP80.1 U17.37 U18.6 | length 882.6
  Top Layer w8: TP80.1@43607.52,42677.17 v1(43643.7,42677.17) ; U17.37@43643.7,42340.55 v1(43643.7,42368.11) U17.37@43643.7,42340.55 ; v1(43643.7,43104.33) U18.6@43643.7,43131.89 v1(43643.7,43104.33)
  Mid-Layer 2 w8: v1(43643.7,42368.11) v1(43643.7,43104.33)
RI16: TP74.1 U18.37 U19.6 | length 1468.9
  Top Layer w8: U18.37@43643.7,43442.91 v1(43643.7,43470.47) ; TP74.1@44380.63,43456.13 v1(44380.63,43492.31) ; U19.6@44935.31,43443.66 v1@44935.31,43471.22
  Mid-Layer 2 w8: v1(43643.7,43470.47) 43704.72,43531.5 43956.69,43531.5 43995.88,43492.31 44614.36,43492.31 44657.48,43535.43 44870.08,43535.43 v1(44935.04,43470.47)
RI17: TP94.1 U19.37 U20.6 | length 882.6
  Top Layer w8: v1(44935.04,42795.28) TP94.1@44971.22,42795.28 ; U20.6@44935.04,42340.55 v1(44935.04,42368.11) U20.6@44935.04,42340.55 ; v1(44935.04,43104.33) U19.37@44935.04,43131.89 v1(44935.04,43104.33)
  Mid-Layer 2 w8: v1(44935.04,42368.11) v1(44935.04,43104.33)
RI18: TP96.1 U20.37 U21.6 | length 882.6
  Top Layer w8: v1(44935.04,41692.91) TP96.1@44971.22,41692.91 ; U21.6@44935.04,41238.19 v1(44935.04,41265.75) U21.6@44935.04,41238.19 ; v1(44935.04,42001.97) U20.37@44935.04,42029.53 v1(44935.04,42001.97)
  Mid-Layer 2 w8: v1(44935.04,41265.75) v1(44935.04,42001.97)
RI19: TP98.1 U21.37 U22.6 | length 882.6
  Top Layer w8: v1(44935.04,40590.55) TP98.1@44971.22,40590.55 ; U22.6@44935.04,40135.83 v1(44935.04,40163.39) U22.6@44935.04,40135.83 ; v1(44935.04,40899.61) U21.37@44935.04,40927.17 v1(44935.04,40899.61)
  Mid-Layer 2 w8: v1(44935.04,40163.39) v1(44935.04,40899.61)
RI20: TP100.1 U22.37 U23.6 | length 1345.9
  Top Layer w8: v1(44934.85,39798.05) U22.37@44934.85,39825.61 ; v1(45580,39742.8) TP100.1@45580,39778.98 ; v1(46104.14,39768.46) U23.6@46104.14,39825.61
  Mid-Layer 2 w8: v1(44934.85,39798.05) 44934.85,39760.15 44952.2,39742.8 46078.48,39742.8 v1(46104.14,39768.46)
RI21: TP114.1 U23.37 U24.6 | length 882.6
  Top Layer w8: TP114.1@46068.15,40472.44 v1(46104.33,40472.44) ; U23.37@46104.33,40135.83 v1(46104.33,40163.39) U23.37@46104.33,40135.83 ; v1(46104.33,40899.61) U24.6@46104.33,40927.17 v1(46104.33,40899.61)
  Mid-Layer 2 w8: v1(46104.33,40163.39) v1(46104.33,40899.61)
RI22: TP116.1 U24.37 U25.6 | length 882.6
  Top Layer w8: TP116.1@46068.15,41574.8 v1(46104.33,41574.8) ; U24.37@46104.33,41238.19 v1(46104.33,41265.75) U24.37@46104.33,41238.19 ; v1(46104.33,42001.97) U25.6@46104.33,42029.53 v1(46104.33,42001.97)
  Mid-Layer 2 w8: v1(46104.33,41265.75) v1(46104.33,42001.97)
RI23: TP118.1 U25.37 U26.6 | length 883.9
  Top Layer w8: TP118.1@46068.15,42677.17 v1(46104.33,42677.17) ; U25.37@46104.33,42340.55 v1(46104.33,42368.11) U25.37@46104.33,42340.55 ; v1(46104.33,43104.33) U26.6@46104.33,43131.89 v1(46104.33,43104.33)
  Mid-Layer 2 w8: v1(46104.33,42368.11) 46104.33,43077.36 46105.85,43078.88 46105.85,43102.81 v1(46104.33,43104.33)
RI24: TP120.1 U26.37 U27.6 | length 1468.9
  Top Layer w8: U26.37@46104.33,43442.91 v1(46104.33,43470.47) ; TP120.1@46841.26,43456.13 v1(46841.26,43492.31) ; U27.6@47395.67,43442.91 v1(47395.67,43470.47)
  Mid-Layer 2 w8: v1(46104.33,43470.47) 46165.35,43531.5 46417.32,43531.5 46456.51,43492.31 47074.99,43492.31 47118.11,43535.43 47330.71,43535.43 v1(47395.67,43470.47)
RI25: TP134.1 U27.37 U28.6 | length 882.6
  Top Layer w8: v1(47395.67,42795.28) TP134.1@47431.85,42795.28 ; U28.6@47395.67,42340.55 v1(47395.67,42368.11) U28.6@47395.67,42340.55 ; v1(47395.67,43104.33) U27.37@47395.67,43131.89 v1(47395.67,43104.33)
  Mid-Layer 2 w8: v1(47395.67,42368.11) v1(47395.67,43104.33)
RI26: TP136.1 U28.37 U29.6 | length 855.1
  Top Layer w8: U29.6@47395.67,41238.19 v1(47395.67,41265.75) ; v1(47395.67,41692.91) TP136.1@47431.85,41692.91 ; v1(47395.67,42001.97) U28.37@47395.67,42029.53 v1(47395.67,42001.97)
  Mid-Layer 2 w8: v1(47395.67,41265.75) v1(47395.67,42001.97)
RI27: TP138.1 U29.37 U30.6 | length 882.6
  Top Layer w8: v1(47395.67,40590.55) TP138.1@47431.85,40590.55 ; U30.6@47395.67,40135.83 v1(47395.67,40163.39) U30.6@47395.67,40135.83 ; v1(47395.67,40899.61) U29.37@47395.67,40927.17 v1(47395.67,40899.61)
  Mid-Layer 2 w8: v1(47395.67,40163.39) v1(47395.67,40899.61)
RI28: TP140.1 U30.37 U31.6 | length 1345
  Top Layer w8: v1(47395.48,39798.05) U30.37@47395.48,39825.61 ; v1(48040,39745) TP140.1@48040,39781.18 ; v1(48564.77,39768.46) U31.6@48564.77,39825.61
  Mid-Layer 2 w8: v1(47395.48,39798.05) 47395.48,39758.56 47409.04,39745 47921.08,39745 48541.31,39745 v1(48564.77,39768.46)
RI29: TP153.1 U31.37 U32.6 | length 827.5
  Top Layer w8: TP153.1@48528.78,40472.44 v1(48564.96,40472.44) ; U31.37@48564.96,40135.83 v1(48564.96,40163.39) ; v1(48564.96,40899.61) U32.6@48564.96,40927.17
  Mid-Layer 2 w8: v1(48564.96,40163.39) v1(48564.96,40899.61)
RI30: TP155.1 U32.37 U33.6 | length 882.6
  Top Layer w8: TP155.1@48528.78,41574.8 v1(48564.96,41574.8) ; U32.37@48564.96,41238.19 v1(48564.96,41265.75) U32.37@48564.96,41238.19 ; v1(48564.96,42001.97) U33.6@48564.96,42029.53 v1(48564.96,42001.97)
  Mid-Layer 2 w8: v1(48564.96,41265.75) v1(48564.96,42001.97)
RI31: TP157.1 U33.37 U34.6 | length 882.6
  Top Layer w8: TP157.1@48528.78,42677.17 v1(48564.96,42677.17) ; U33.37@48564.96,42340.55 v1(48564.96,42368.11) U33.37@48564.96,42340.55 ; v1(48564.96,43104.33) U34.6@48564.96,43131.89 v1(48564.96,43104.33)
  Mid-Layer 2 w8: v1(48564.96,42368.11) v1(48564.96,43104.33)
RI32: R21.1 U34.37 | length 72.8
  Top Layer w9: R21.1@48541.34,43505.91 48541.34,43483.66 48564.96,43460.04 U34.37@48564.96,43442.91
RST: C31.1 R18.1 TP28.1 U3.10 | length 356.1
  Top Layer w10: v1(39820.87,43649.61) R18.1@39820.87,43712.6 ; R18.1@39820.87,43724.41 TP28.1@39860,43724.41 ; U3.10@39935.04,43442.91 v1(39935.04,43466.54)
  Mid-Layer 2 w10: v1(39820.87,43649.61) 39820.87,43580.71 v1(39935.04,43466.54)
RST1: TP17.1 U3.33 U4.10 | length 827.5
  Top Layer w8: TP17.1@39898.86,42795.28 v1(39935.04,42795.28) ; U4.10@39935.04,42340.55 v1(39935.04,42368.11) ; v1(39935.04,43104.33) U3.33@39935.04,43131.89
  Mid-Layer 2 w8: v1(39935.04,42368.11) v1(39935.04,43104.33)
RST2: TP19.1 U4.33 U5.10 | length 882.6
  Top Layer w8: TP19.1@39898.86,41692.91 v1(39935.04,41692.91) ; U5.10@39935.04,41238.19 v1(39935.04,41265.75) U5.10@39935.04,41238.19 ; v1(39935.04,42001.97) U4.33@39935.04,42029.53 v1(39935.04,42001.97)
  Mid-Layer 2 w8: v1(39935.04,41265.75) v1(39935.04,42001.97)
RST3: TP21.1 U5.33 U6.10 | length 882.6
  Top Layer w8: TP21.1@39898.86,40590.55 v1(39935.04,40590.55) ; U6.10@39935.04,40135.83 v1(39935.04,40163.39) U6.10@39935.04,40135.83 ; v1(39935.04,40899.61) U5.33@39935.04,40927.17 v1(39935.04,40899.61)
  Mid-Layer 2 w8: v1(39935.04,40163.39) v1(39935.04,40899.61)
RST4: TP23.1 U6.33 U7.10 | length 1532
  Top Layer w8: v1(39935.04,39797.24) U6.33@39935.04,39824.8 ; v1(40600,39702) TP23.1@40636.18,39702 ; v1(41261.81,39767.66) U7.10@41261.81,39824.8
  Mid-Layer 2 w8: v1(39935.04,39797.24) 39935.04,39767.11 40000.15,39702 41196.15,39702 v1(41261.81,39767.66)
RST5: TP41.1 U7.33 U8.10 | length 882.6
  Top Layer w8: v1(41261.81,40472.44) TP41.1@41297.99,40472.44 ; U7.33@41261.81,40135.83 v1(41261.81,40163.39) U7.33@41261.81,40135.83 ; v1(41261.81,40899.61) U8.10@41261.81,40927.17 v1(41261.81,40899.61)
  Mid-Layer 2 w8: v1(41261.81,40163.39) v1(41261.81,40899.61)
RST6: TP43.1 U8.33 U9.10 | length 882.6
  Top Layer w8: v1(41261.81,41574.8) TP43.1@41297.99,41574.8 ; U8.33@41261.81,41238.19 v1(41261.81,41265.75) U8.33@41261.81,41238.19 ; v1(41261.81,42001.97) U9.10@41261.81,42029.53 v1(41261.81,42001.97)
  Mid-Layer 2 w8: v1(41261.81,41265.75) v1(41261.81,42001.97)
RST7: TP45.1 U9.33 U10.10 | length 882.6
  Top Layer w8: v1(41261.81,42677.17) TP45.1@41297.99,42677.17 ; U9.33@41261.81,42340.55 v1(41261.81,42368.11) U9.33@41261.81,42340.55 ; v1(41261.81,43104.33) U10.10@41261.81,43131.89 v1(41261.81,43104.33)
  Mid-Layer 2 w8: v1(41261.81,42368.11) v1(41261.81,43104.33)
RST8: TP47.1 U10.33 U11.10 | length 1285
  Top Layer w8: U10.33@41261.81,43442.91 v1(41261.81,43470.47) ; TP47.1@41850,43417.13 v1(41850,43453.31) ; U11.10@42395.67,43442.91 v1(42395.67,43470.47)
  Mid-Layer 2 w8: v1(41261.81,43470.47) 41291.34,43500 41472.44,43500 41519.13,43453.31 42169.85,43453.31 42212.6,43496.06 42370.08,43496.06 v1(42395.67,43470.47)
RST9: TP61.1 U11.33 U12.10 | length 882.6
  Top Layer w8: TP61.1@42359.49,42795.28 v1(42395.67,42795.28) ; U12.10@42395.67,42340.55 v1(42395.67,42368.11) U12.10@42395.67,42340.55 ; v1(42395.67,43104.33) U11.33@42395.67,43131.89 v1(42395.67,43104.33)
  Mid-Layer 2 w8: v1(42395.67,42368.11) v1(42395.67,43104.33)
RST10: TP63.1 U12.33 U13.10 | length 882.6
  Top Layer w8: TP63.1@42359.49,41692.91 v1(42395.67,41692.91) ; U13.10@42395.67,41238.19 v1(42395.67,41265.75) U13.10@42395.67,41238.19 ; v1(42395.67,42001.97) U12.33@42395.67,42029.53 v1(42395.67,42001.97)
  Mid-Layer 2 w8: v1(42395.67,41265.75) v1(42395.67,42001.97)
RST11: TP65.1 U13.33 U14.10 | length 882.6
  Top Layer w8: TP65.1@42359.49,40590.55 v1(42395.67,40590.55) ; U14.10@42395.67,40135.83 v1(42395.67,40163.39) U14.10@42395.67,40135.83 ; v1(42395.67,40899.61) U13.33@42395.67,40927.17 v1(42395.67,40899.61)
  Mid-Layer 2 w8: v1(42395.67,40163.39) v1(42395.67,40899.61)
RST12: TP67.1 U14.33 U15.10 | length 1533.4
  Top Layer w8: v1(42395.48,39798.05) U14.33@42395.48,39825.61 ; TP67.1@43060.44,39666.62 v1(43060.44,39702.8) ; v1(43722.44,39766.36) U15.10@43722.44,39824.8
  Mid-Layer 2 w8: v1(42395.48,39798.05) 42395.48,39760.57 42453.25,39702.8 43658.89,39702.8 v1@43720,39763.92
RST13: TP83.1 U15.33 U16.10 | length 855.1
  Top Layer w8: U15.33@43722.44,40135.83 v1(43722.44,40163.39) ; v1(43722.44,40472.44) TP83.1@43758.62,40472.44 ; v1(43722.44,40899.61) U16.10@43722.44,40927.17 v1(43722.44,40899.61)
  Mid-Layer 2 w8: v1(43722.44,40163.39) v1(43722.44,40899.61)
RST14: TP85.1 U16.33 U17.10 | length 882.6
  Top Layer w8: v1(43722.44,41574.8) TP85.1@43758.62,41574.8 ; U16.33@43722.44,41238.19 v1(43722.44,41265.75) U16.33@43722.44,41238.19 ; v1(43722.44,42001.97) U17.10@43722.44,42029.53 v1(43722.44,42001.97)
  Mid-Layer 2 w8: v1(43722.44,41265.75) v1(43722.44,42001.97)
RST15: TP87.1 U17.33 U18.10 | length 882.6
  Top Layer w8: v1(43722.44,42677.17) TP87.1@43758.62,42677.17 ; U17.33@43722.44,42340.55 v1(43722.44,42368.11) U17.33@43722.44,42340.55 ; v1(43722.44,43104.33) U18.10@43722.44,43131.89 v1(43722.44,43104.33)
  Mid-Layer 2 w8: v1(43722.44,42368.11) v1(43722.44,43104.33)
RST16: TP81.1 U18.33 U19.10 | length 1285
  Top Layer w8: U18.33@43722.44,43442.91 v1(43722.44,43470.47) ; TP81.1@44310.63,43417.13 v1(44310.63,43453.31) ; U19.10@44856.57,43443.66 v1@44856.57,43471.22
  Mid-Layer 2 w8: v1(43722.44,43470.47) 43751.97,43500 43933.07,43500 43979.76,43453.31 44630.48,43453.31 44673.23,43496.06 44830.71,43496.06 v1(44856.3,43470.47)
RST17: TP101.1 U19.33 U20.10 | length 882.6
  Top Layer w8: TP101.1@44820.12,42795.28 v1(44856.3,42795.28) ; U20.10@44856.3,42340.55 v1(44856.3,42368.11) U20.10@44856.3,42340.55 ; v1(44856.3,43104.33) U19.33@44856.3,43131.89 v1(44856.3,43104.33)
  Mid-Layer 2 w8: v1(44856.3,42368.11) v1(44856.3,43104.33)
RST18: TP103.1 U20.33 U21.10 | length 855.1
  Top Layer w8: TP103.1@44820.12,41692.91 v1(44856.3,41692.91) ; U21.10@44856.3,41238.19 v1(44856.3,41265.75) ; v1(44856.3,42001.97) U20.33@44856.3,42029.53 v1(44856.3,42001.97)
  Mid-Layer 2 w8: v1(44856.3,41265.75) v1(44856.3,42001.97)
RST19: TP105.1 U21.33 U22.10 | length 882.6
  Top Layer w8: TP105.1@44820.12,40590.55 v1(44856.3,40590.55) ; U22.10@44856.3,40135.83 v1(44856.3,40163.39) U22.10@44856.3,40135.83 ; v1(44856.3,40899.61) U21.33@44856.3,40927.17 v1(44856.3,40899.61)
  Mid-Layer 2 w8: v1(44856.3,40163.39) v1(44856.3,40899.61)
RST20: TP107.1 U22.33 U23.10 | length 1538.6
  Top Layer w8: v1(44856.11,39798.05) U22.33@44856.11,39825.61 ; TP107.1@45520,39663.82 v1(45520,39700) ; v1(46182.88,39768.46) U23.10@46182.88,39825.61
  Mid-Layer 2 w8: v1(44856.11,39798.05) 44856.11,39760.57 44916.68,39700 46114.42,39700 v1(46182.88,39768.46)
RST21: TP121.1 U23.33 U24.10 | length 882.6
  Top Layer w8: v1(46183.07,40472.44) TP121.1@46219.25,40472.44 ; U23.33@46183.07,40135.83 v1(46183.07,40163.39) U23.33@46183.07,40135.83 ; v1(46183.07,40899.61) U24.10@46183.07,40927.17 v1(46183.07,40899.61)
  Mid-Layer 2 w8: v1(46183.07,40163.39) v1(46183.07,40899.61)
RST22: TP123.1 U24.33 U25.10 | length 882.6
  Top Layer w8: v1(46183.07,41574.8) TP123.1@46219.25,41574.8 ; U24.33@46183.07,41238.19 v1(46183.07,41265.75) U24.33@46183.07,41238.19 ; v1(46183.07,42001.97) U25.10@46183.07,42029.53 v1(46183.07,42001.97)
  Mid-Layer 2 w8: v1(46183.07,41265.75) v1(46183.07,42001.97)
RST23: TP125.1 U25.33 U26.10 | length 882.6
  Top Layer w8: v1(46183.07,42677.17) TP125.1@46219.25,42677.17 ; U25.33@46183.07,42340.55 v1(46183.07,42368.11) U25.33@46183.07,42340.55 ; v1(46183.07,43104.33) U26.10@46183.07,43131.89 v1(46183.07,43104.33)
  Mid-Layer 2 w8: v1(46183.07,42368.11) v1(46183.07,43104.33)
RST24: TP127.1 U26.33 U27.10 | length 1285
  Top Layer w8: U26.33@46183.07,43442.91 v1(46183.07,43470.47) ; TP127.1@46771.26,43417.13 v1(46771.26,43453.31) ; U27.10@47316.93,43442.91 v1(47316.93,43470.47)
  Mid-Layer 2 w8: v1(46183.07,43470.47) 46212.6,43500 46393.7,43500 46440.39,43453.31 47091.11,43453.31 47133.86,43496.06 47291.34,43496.06 v1(47316.93,43470.47)
RST25: TP141.1 U27.33 U28.10 | length 882.6
  Top Layer w8: TP141.1@47280.75,42795.28 v1(47316.93,42795.28) ; U28.10@47316.93,42340.55 v1(47316.93,42368.11) U28.10@47316.93,42340.55 ; v1(47316.93,43104.33) U27.33@47316.93,43131.89 v1(47316.93,43104.33)
  Mid-Layer 2 w8: v1(47316.93,42368.11) v1(47316.93,43104.33)
RST26: TP143.1 U28.33 U29.10 | length 882.6
  Top Layer w8: TP143.1@47280.75,41692.91 v1(47316.93,41692.91) ; U29.10@47316.93,41238.19 v1(47316.93,41265.75) U29.10@47316.93,41238.19 ; v1(47316.93,42001.97) U28.33@47316.93,42029.53 v1(47316.93,42001.97)
  Mid-Layer 2 w8: v1(47316.93,41265.75) v1(47316.93,42001.97)
RST27: TP145.1 U29.33 U30.10 | length 882.6
  Top Layer w8: TP145.1@47280.75,40590.55 v1(47316.93,40590.55) ; U30.10@47316.93,40135.83 v1(47316.93,40163.39) U30.10@47316.93,40135.83 ; v1(47316.93,40899.61) U29.33@47316.93,40927.17 v1(47316.93,40899.61)
  Mid-Layer 2 w8: v1(47316.93,40163.39) v1(47316.93,40899.61)
RST28: TP147.1 U30.33 U31.10 | length 1545.4
  Top Layer w8: v1(47316.74,39798.05) U30.33@47316.74,39825.61 ; TP147.1@47980,39663.82 v1(47980,39700) ; v1(48640,39770) 48643.51,39773.51 U31.10@48643.51,39825.61
  Mid-Layer 2 w8: v1(47316.74,39798.05) 47313.43,39794.73 47313.43,39760.39 47373.81,39700 48570,39700 v1(48640,39770) v1@48643.51,39773.51
RST29: TP158.1 U31.33 U32.10 | length 882.6
  Top Layer w8: v1(48643.7,40472.44) TP158.1@48679.88,40472.44 ; U31.33@48643.7,40135.83 v1(48643.7,40163.39) U31.33@48643.7,40135.83 ; v1(48643.7,40899.61) U32.10@48643.7,40927.17 v1(48643.7,40899.61)
  Mid-Layer 2 w8: v1(48643.7,40163.39) v1(48643.7,40899.61)
RST30: TP160.1 U32.33 U33.10 | length 882.6
  Top Layer w8: v1(48643.7,41574.8) TP160.1@48679.88,41574.8 ; U32.33@48643.7,41238.19 v1(48643.7,41265.75) U32.33@48643.7,41238.19 ; v1(48643.7,42001.97) U33.10@48643.7,42029.53 v1(48643.7,42001.97)
  Mid-Layer 2 w8: v1(48643.7,41265.75) v1(48643.7,42001.97)
RST31: TP162.1 U33.33 U34.10 | length 882.6
  Top Layer w8: v1(48643.7,42677.17) TP162.1@48679.88,42677.17 ; U33.33@48643.7,42340.55 v1(48643.7,42368.11) U33.33@48643.7,42340.55 ; v1(48643.7,43104.33) U34.10@48643.7,43131.89 v1(48643.7,43104.33)
  Mid-Layer 2 w8: v1(48643.7,42368.11) v1(48643.7,43104.33)
RXD: J1.3 TP27.1 U3.6 | length 2134.6
  Top Layer w8: TP27.1@40418.82,43700 v1(40455,43700)
  Top Layer w9: v1(40013.22,43490.34) 40013.46,43490.09 40013.46,43443.23 U3.6@40013.78,43442.91
  Mid-Layer 1 w9: v1(40677.52,44620) J1.3@40677.52,45130
  Mid-Layer 2 w10: v1(40013.22,43490.34) 40028.27,43490.34 40062.94,43525 40280,43525 40500,43745 40500,43955 40677.52,44132.52 v1(40677.52,44620)
TEMP_SCL: J1.6 U42.2 | length 5866.3
  Top Layer w20: U42.2@44315,41697.52 v1(44315,41749.8)
  Mid-Layer 1 w20: J1.6@40913.74,45130 40913.74,45046.26 41120,44840 41530,44840 41935,44435 41935,44060 42335,43660 42745,43660 42910,43495 42910,42225 43335,41800 44264.8,41800 v1(44315,41749.8)
TEMP_SDA: J1.7 R74.1 U42.1 | length 5900.1
  Top Layer w20: U42.1@44365,41697.52 R74.1@44365,41795.47
  Mid-Layer 1 w20: J1.7@40992.48,45130 40992.48,45032.52 41150,44875 41550,44875 41970,44455 41970,44070 42345,43695 42760,43695 42943,43512 42943,43467.44 42945,43465.45 42945,42235 43345,41835 44279.8,41835 v1(44365,41749.8)
TXD: J1.5 R15.2 TP26.1 U3.5 | length 2234.5
  Top Layer w8: TP26.1@40413.82,43625 v1(40450,43625)
  Top Layer w9: U3.5@40033.46,43442.91 40033.46,43466.54 v1@40044.64,43477.71
  Top Layer w10: R15.2@40520,43669.53 v1(40520,43695)
  Mid-Layer 1 w10: v1(40835,44620) J1.5@40835,45130
  Mid-Layer 2 w10: v1(40045,43475) 40045,43478.07 40071.93,43505 40330,43505 v1(40520,43695) 40520,43945 40695,44120 40695,44480 v1(40835,44620)
VDD1: C1.1 C2.1 C3.1 C4.1 C8.2 C9.2 C17.1 C18.1 C19.2 C20.2 C44.2 C45.2 C46.2 C47.2 C48.2 C49.2 C50.2 C51.2 C52.2 C53.2 C54.2 C55.2 C56.2 C57.2 C58.2 C59.2 C60.2 C61.2 C62.2 C63.2 C64.2 C65.2 C66.2 C67.2 C68.2 C69.2 C70.2 C71.2 C72.2 C73.2 C74.2 C75.2 C76.2 C77.2 C78.2 C79.2 C80.2 C81.2 C82.2 C83.2 C84.2 C85.2 C86.2 C87.2 C108.2 C109.2 C110.2 C111.2 C112.2 C113.2 C114.2 C115.2 C116.2 C117.2 C118.2 C119.2 C120.2 C121.2 C122.2 C123.2 C124.2 C125.2 C126.2 C127.2 C128.2 C129.2 C130.2 C131.2 C132.2 C133.2 C134.2 C135.2 C136.2 C137.2 C138.2 C139.2 C140.2 C141.2 C142.2 C143.2 C144.2 C145.2 C146.2 C147.2 C148.2 C149.2 C150.2 C151.2 L1.2 R3.1 TP1.1 U3.4 U3.7 U3.11 U3.17 U3.21 U3.25 U3.32 U3.36 U3.40 U3.47 U3.51 U4.4 U4.7 U4.11 U4.17 U4.21 U4.25 U4.32 U4.36 U4.40 U4.47 U4.51 U5.4 U5.7 U5.11 U5.17 U5.21 U5.25 U5.32 U5.36 U5.40 U5.47 U5.51 U6.4 U6.7 U6.11 U6.17 U6.21 U6.25 U6.32 U6.36 U6.40 U6.47 U6.51 U7.4 U7.7 U7.11 U7.17 U7.21 U7.25 U7.32 U7.36 U7.40 U7.47 U7.51 U8.4 U8.7 U8.11 U8.17 U8.21 U8.25 U8.32 U8.36 U8.40 U8.47 U8.51 U9.4 U9.7 U9.11 U9.17 U9.21 U9.25 U9.32 U9.36 U9.40 U9.47 U9.51 U10.4 U10.7 U10.11 U10.17 U10.21 U10.25 U10.32 U10.36 U10.40 U10.47 U10.51 | length 788.6
  Top Layer w11: v1(41110.24,43956.69) C3.1@41110.24,44023.62
  Top Layer w15: R3.1@40549.21,43842.52 v1(40574.8,43842.52)
  Mid-Layer 2 w15: v1(40574.8,43842.52) 40783.46,43842.52 40897.64,43956.69 v1(41110.24,43956.69)
  Bottom Layer w10: v1(40633.86,43956.69) C1.1@40633.86,44070
VDD2: C152.1 C153.1 C154.2 C155.2 C176.2 C177.2 C178.2 C179.2 C180.2 C181.2 C182.2 C183.2 C184.2 C185.2 C186.2 C187.2 C188.2 C189.2 C190.2 C191.2 C192.2 C193.2 C194.2 C195.2 C196.2 C197.2 C198.2 C199.2 C200.2 C201.2 C202.2 C203.2 C204.2 C205.2 C206.2 C207.2 C208.2 C209.2 C210.2 C211.2 C212.2 C213.2 C214.2 C215.2 C216.2 C217.2 C218.2 C219.2 C240.2 C241.2 C242.2 C243.2 C244.2 C245.2 C246.2 C247.2 C248.2 C249.2 C250.2 C251.2 C252.2 C253.2 C254.2 C255.2 C256.2 C257.2 C258.2 C259.2 C260.2 C261.2 C262.2 C263.2 C264.2 C265.2 C266.2 C267.2 C268.2 C269.2 C270.2 C271.2 C272.2 C273.2 C274.2 C275.2 C276.2 C277.2 C278.2 C279.2 C280.2 C281.2 C282.2 C283.2 C555.2 C556.2 C596.1 C597.1 C598.1 C599.1 L2.2 R66.1 TP164.1 U11.4 U11.7 U11.11 U11.17 U11.21 U11.25 U11.32 U11.36 U11.40 U11.47 U11.51 U12.4 U12.7 U12.11 U12.17 U12.21 U12.25 U12.32 U12.36 U12.40 U12.47 U12.51 U13.4 U13.7 U13.11 U13.17 U13.21 U13.25 U13.32 U13.36 U13.40 U13.47 U13.51 U14.4 U14.7 U14.11 U14.17 U14.21 U14.25 U14.32 U14.36 U14.40 U14.47 U14.51 U15.4 U15.7 U15.11 U15.17 U15.21 U15.25 U15.32 U15.36 U15.40 U15.47 U15.51 U16.4 U16.7 U16.11 U16.17 U16.21 U16.25 U16.32 U16.36 U16.40 U16.47 U16.51 U17.4 U17.7 U17.11 U17.17 U17.21 U17.25 U17.32 U17.36 U17.40 U17.47 U17.51 U18.4 U18.7 U18.11 U18.17 U18.21 U18.25 U18.32 U18.36 U18.40 U18.47 U18.51 | length 773.6
  Top Layer w11: v1(43452.76,43956.69) C597.1@43452.76,44023.62
  Top Layer w15: R66.1@42891.73,43842.52 v1(42917.32,43842.52)
  Mid-Layer 2 w15: v1(42917.32,43842.52) 43125.98,43842.52 43240.16,43956.69 v1(43452.76,43956.69)
  Bottom Layer w10: v1(42976.38,43956.69) C598.1@42976.38,44055
VDD3: C284.1 C285.1 C286.2 C287.2 C308.2 C309.2 C310.2 C311.2 C312.2 C313.2 C314.2 C315.2 C316.2 C317.2 C318.2 C319.2 C320.2 C321.2 C322.2 C323.2 C324.2 C325.2 C326.2 C327.2 C328.2 C329.2 C330.2 C331.2 C332.2 C333.2 C334.2 C335.2 C336.2 C337.2 C338.2 C339.2 C340.2 C341.2 C342.2 C343.2 C344.2 C345.2 C346.2 C347.2 C348.2 C349.2 C350.2 C351.2 C372.2 C373.2 C374.2 C375.2 C376.2 C377.2 C378.2 C379.2 C380.2 C381.2 C382.2 C383.2 C384.2 C385.2 C386.2 C387.2 C388.2 C389.2 C390.2 C391.2 C392.2 C393.2 C394.2 C395.2 C396.2 C397.2 C398.2 C399.2 C400.2 C401.2 C402.2 C403.2 C404.2 C405.2 C406.2 C407.2 C408.2 C409.2 C410.2 C411.2 C412.2 C413.2 C414.2 C415.2 C564.1 C565.1 C566.1 C567.1 C571.2 C572.2 L3.2 R38.1 TP168.1 U19.4 U19.7 U19.11 U19.17 U19.21 U19.25 U19.32 U19.36 U19.40 U19.47 U19.51 U20.4 U20.7 U20.11 U20.17 U20.21 U20.25 U20.32 U20.36 U20.40 U20.47 U20.51 U21.4 U21.7 U21.11 U21.17 U21.21 U21.25 U21.32 U21.36 U21.40 U21.47 U21.51 U22.4 U22.7 U22.11 U22.17 U22.21 U22.25 U22.32 U22.36 U22.40 U22.47 U22.51 U23.4 U23.7 U23.11 U23.17 U23.21 U23.25 U23.32 U23.36 U23.40 U23.47 U23.51 U24.4 U24.7 U24.11 U24.17 U24.21 U24.25 U24.32 U24.36 U24.40 U24.47 U24.51 U25.4 U25.7 U25.11 U25.17 U25.21 U25.25 U25.32 U25.36 U25.40 U25.47 U25.51 U26.4 U26.7 U26.11 U26.17 U26.21 U26.25 U26.32 U26.36 U26.40 U26.47 U26.51 | length 788.6
  Top Layer w11: v1(45897.64,43956.69) C566.1@45897.64,44023.62
  Top Layer w15: R38.1@45336.61,43842.52 v1(45362.2,43842.52)
  Mid-Layer 2 w15: v1(45362.2,43842.52) 45570.87,43842.52 45685.04,43956.69 v1(45897.64,43956.69)
  Bottom Layer w10: v1(45421.26,43956.69) C564.1@45421.26,44070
